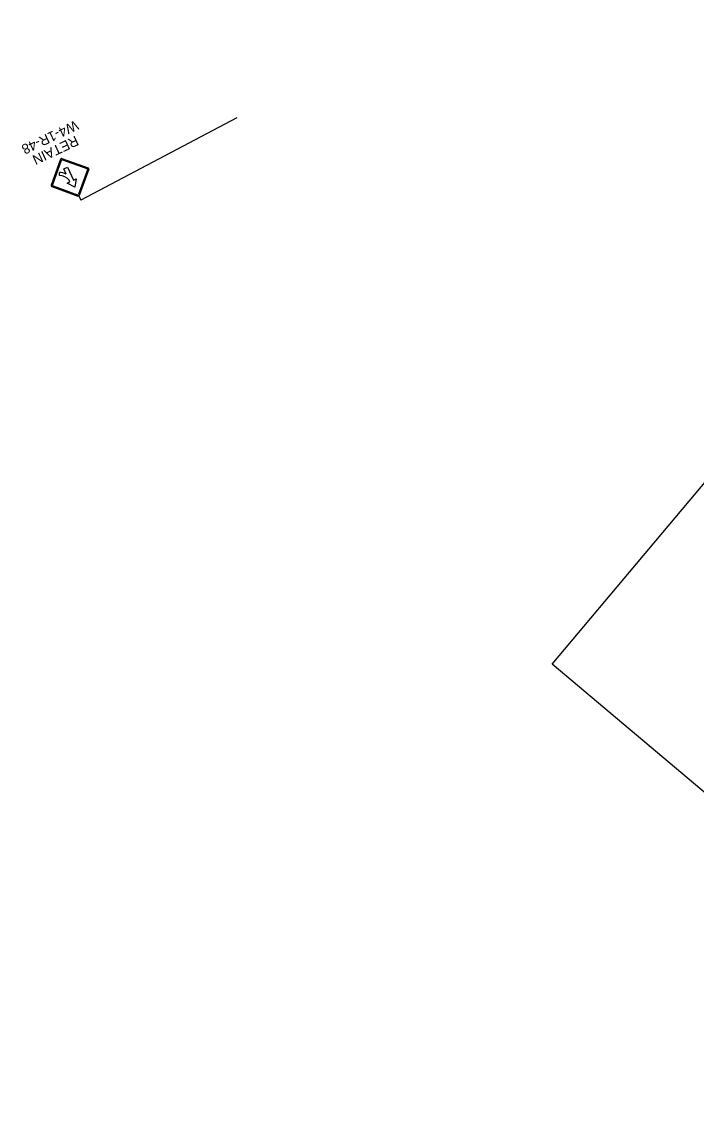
# Model space of a CAD drawing. Extents: x 2001876 to 2025694, y 804561 to 868938.
# Drawn here: x 2010363 to 2011719, y 821154 to 823329 of the extents above; entities that cross this region are included whole.
import ezdxf

# ---------------------------------------------------------------- set-up
doc = ezdxf.new("R2010")
doc.units = 0
for name, color, linetype in [('RD_SHT_ShtClip', 7, 'Continuous'), ('TR SN EXTRUDED PANEL SIGNS - GROUND MOUNTED', 7, 'Continuous'), ('TR SN EXTRUDED PANEL SIGNS- MOUNTED OVERHEAD', 7, 'Continuous'), ('TR SN FLAT SHEET - TYPE III - FIXED SZ and MSG SIGN', 7, 'Continuous')]:
    doc.layers.add(name, color=color, linetype=linetype)

msp = doc.modelspace()

# ---------------------------------------------------------------- linework, layer by layer
at = {"layer": 'RD_SHT_ShtClip'}
for p, q in [((2011429.3, 822038.4), (2012671.5, 823516.1)), ((2016066.1, 818140.6), (2011429.3, 822038.4))]:
    msp.add_line(p, q, dxfattribs=at)
at = {"layer": 'TR SN EXTRUDED PANEL SIGNS - GROUND MOUNTED'}
msp.add_line((2010795.8, 823135.9), (2010482.3, 822970.6), dxfattribs=at)
at = {"layer": 'TR SN EXTRUDED PANEL SIGNS- MOUNTED OVERHEAD'}
msp.add_line((2010477.8, 822978.9), (2010482.3, 822970.6), dxfattribs=at)
at = {"layer": 'TR SN FLAT SHEET - TYPE III - FIXED SZ and MSG SIGN'}
for p, q in [((2010441.4, 823053.1), (2010422.4, 823000.4)), ((2010444, 823054.3), (2010496.7, 823035.3)), ((2010445.2, 823051.7), (2010494.1, 823034.1)), ((2010442.6, 823050.5), (2010425, 823001.6)), ((2010447.9, 823033.4), (2010455.2, 823036.8)), ((2010452.9, 823022.9), (2010447.9, 823033.4)), ((2010455.2, 823036.8), (2010467.5, 823010.5)), ((2010495.3, 823031.5), (2010477.7, 822982.6)), ((2010497.9, 823032.7), (2010478.9, 822980)), ((2010439, 823020.3), (2010439.1, 823026.3)), ((2010460.3, 823007.1), (2010458.7, 823010.5)), ((2010467.5, 823010.5), (2010473, 823013.1)), ((2010473, 823013.1), (2010469.8, 822996.3)), ((2010423.6, 822997.8), (2010476.3, 822978.8)), ((2010426.2, 822999), (2010475.1, 822981.4)), ((2010454.9, 823004.6), (2010460.3, 823007.1)), ((2010469.8, 822996.3), (2010454.9, 823004.6))]:
    msp.add_line(p, q, dxfattribs=at)
for centre, radius, start, end in [((2010443.3, 823052.4), 2, 70.1529, 160.1529), ((2010444.5, 823049.8), 2, 70.1513, 160.1514), ((2010493.4, 823032.2), 2, 340.1529, 70.1558), ((2010496, 823033.4), 2, 340.1529, 70.1537), ((2010438.8, 822995.2), 25.1, 37.5011, 89.4341), ((2010438.8, 822995.2), 31.1, 63.0886, 89.4341), ((2010424.3, 822999.7), 2, 160.1529, 250.1486), ((2010426.9, 823000.9), 2, 160.1529, 250.1508), ((2010475.8, 822983.3), 2, 250.1543, 340.1529), ((2010477, 822980.7), 2, 250.1538, 340.1529)]:
    msp.add_arc(centre, radius, start, end, dxfattribs=at)

# ---------------------------------------------------------------- texts
at = {"layer": 'TR SN EXTRUDED PANEL SIGNS - GROUND MOUNTED'}
for s, p in [('W4-1R-48', (2010471.2, 823131.6)), ('RETAIN', (2010471.5, 823100.5))]:
    msp.add_text(s, height=20, rotation=205.1274, dxfattribs=at).set_placement(p)

doc.saveas('drawing.dxf')
